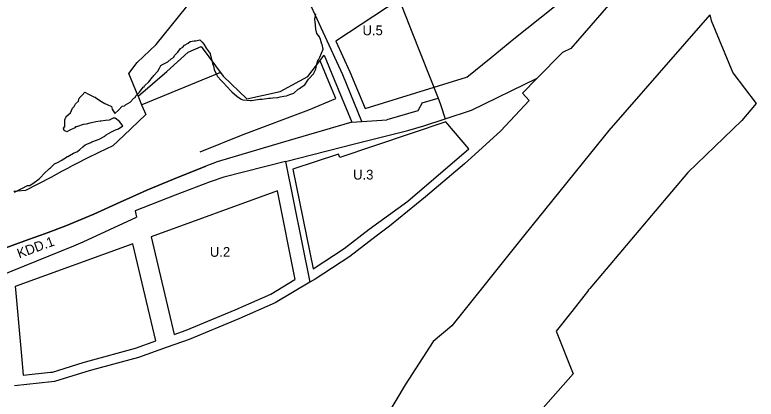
# Model space of a CAD drawing. Extents: x 7423571 to 7425893, y 5544590 to 5545833.
# Drawn here: x 7424447.1 to 7424826.9, y 5544859.3 to 5545056.2 of the extents above; entities that cross this region are included whole.
import ezdxf

# ---------------------------------------------------------------- set-up
doc = ezdxf.new("R2010")
doc.units = 0
for name, color, linetype in [('Default', 7, 'Continuous'), ('linie_rozgraniczające', 7, 'Continuous'), ('linie_zabudowy_nieprzekraczalne', 7, 'Continuous'), ('linie_zabudowy_obowiązujace', 7, 'Continuous'), ('oznaczenia_przeznaczen', 7, 'Continuous')]:
    doc.layers.add(name, color=color, linetype=linetype)

msp = doc.modelspace()

# ---------------------------------------------------------------- linework, layer by layer
at = {"layer": 'Default'}
msp.add_lwpolyline([(7424446.81, 5544965.29), (7424449.22, 5544966.56), (7424449.88, 5544966.97), (7424450.11, 5544967.05), (7424450.64, 5544967.3), (7424453.54, 5544968.7), (7424454.81, 5544968.78), (7424457.02, 5544970.3), (7424458.82, 5544971.77), (7424459.67, 5544972.43), (7424459.83, 5544972.52), (7424460, 5544972.69), (7424462.19, 5544975.14), (7424464.48, 5544977.19), (7424464.87, 5544977.48), (7424465.25, 5544977.9), (7424467.44, 5544979.92), (7424469.34, 5544980.78), (7424470.88, 5544981.57), (7424473.57, 5544983.24), (7424473.88, 5544983.6), (7424474.22, 5544983.71), (7424475.07, 5544984.17), (7424477.14, 5544985.4), (7424479.12, 5544986.28), (7424480.45, 5544987.17), (7424481.91, 5544988.59), (7424483.02, 5544989.6), (7424483.98, 5544989.97), (7424486.08, 5544990.9), (7424486.57, 5544991.14), (7424488.9, 5544992.07), (7424490.33, 5544992.48), (7424493.16, 5544994.05), (7424493.39, 5544994.47), (7424493.79, 5544994.72), (7424495, 5544995.36), (7424496.64, 5544996.28), (7424498.69, 5544997.23), (7424500.16, 5544997.84), (7424502.46, 5544999.43), (7424500.71, 5545001.55), (7424498.45, 5545003.31), (7424497.43, 5545003.21), (7424495.44, 5545002.19), (7424493.49, 5545002.07), (7424491.34, 5545001.82), (7424490.79, 5545001.67), (7424488.51, 5545001.45), (7424486.42, 5545000.9), (7424485.51, 5545000.71), (7424483.56, 5545000.24), (7424482.15, 5545000.02), (7424479.09, 5544998.96), (7424478.61, 5544998.86), (7424478.17, 5544998.89), (7424477.72, 5544998.42), (7424474.94, 5544997.05), (7424473.71, 5544996.37), (7424472.4, 5544996.93), (7424472, 5544998.19), (7424472.74, 5544999.09), (7424472.73, 5545002.49), (7424472.94, 5545003.23), (7424473.12, 5545003.54), (7424473.39, 5545004.13), (7424475.6, 5545006.06), (7424476.61, 5545008.39), (7424477.39, 5545009.22), (7424478.14, 5545010.57), (7424479.61, 5545011.98), (7424480.07, 5545013.53), (7424481.51, 5545015.04), (7424482.9, 5545016.54), (7424484.8, 5545015.59), (7424487.62, 5545014.21), (7424488, 5545014.02), (7424488.16, 5545014.02), (7424488.47, 5545013.87), (7424491.09, 5545011.98), (7424493.14, 5545010.83), (7424494.29, 5545010.23), (7424496.6, 5545009.2), (7424496.91, 5545007.86), (7424498.35, 5545005.63), (7424500.16, 5545007.46), (7424502.02, 5545009.42), (7424503, 5545009.65), (7424503.19, 5545009.69), (7424503.77, 5545010.08), (7424506.18, 5545011.53), (7424508.04, 5545013.46), (7424508.76, 5545013.96), (7424509.1, 5545014.71), (7424511, 5545016.7), (7424512.82, 5545019.13), (7424513.26, 5545019.43), (7424513.5, 5545019.89), (7424515.78, 5545021.91), (7424517.61, 5545024.34), (7424518.02, 5545024.66), (7424518.28, 5545025.09), (7424520.3, 5545027.36), (7424521.16, 5545028.95), (7424521.95, 5545030.24), (7424522.16, 5545030.46), (7424522.36, 5545030.57), (7424523.01, 5545030.95), (7424525.5, 5545032.19), (7424527.24, 5545033.63), (7424528.28, 5545034.43), (7424529.01, 5545035.53), (7424530.63, 5545037.07), (7424532.03, 5545038.96), (7424533.08, 5545039.62), (7424534.08, 5545040.74), (7424535.92, 5545041.81), (7424536.89, 5545042.56), (7424538.87, 5545042.94), (7424539.88, 5545042.97), (7424541.85, 5545043.5), (7424543.04, 5545042.24), (7424543.87, 5545041.14), (7424545.08, 5545039.24), (7424547.14, 5545036.49), (7424547.2, 5545036.32), (7424547.21, 5545036.27), (7424547.23, 5545036.19), (7424548.09, 5545032.07), (7424548.32, 5545031.31), (7424548.8, 5545029.94), (7424549.28, 5545028.15), (7424550.06, 5545026.38), (7424550.86, 5545024.65), (7424552.71, 5545022.55), (7424553.28, 5545022.06), (7424553.88, 5545021.53), (7424555.68, 5545019.44), (7424557.93, 5545017.12), (7424558.13, 5545016.89), (7424558.31, 5545016.71), (7424560.73, 5545014.49), (7424563.1, 5545013.08), (7424563.93, 5545012.75), (7424567.83, 5545012.4), (7424568.14, 5545012.32), (7424568.33, 5545012.3), (7424572.38, 5545013), (7424573.11, 5545012.97), (7424573.78, 5545013), (7424577.09, 5545013.47), (7424578.09, 5545013.53), (7424579.23, 5545013.7), (7424581.8, 5545013.94), (7424583.07, 5545014.15), (7424584.87, 5545014.6), (7424586.2, 5545014.69), (7424588.03, 5545015.36), (7424589.95, 5545016.04), (7424592.26, 5545018.09), (7424592.66, 5545018.35), (7424592.9, 5545018.57), (7424594.22, 5545019.52), (7424595.67, 5545020.39), (7424597.23, 5545022.78), (7424597.61, 5545023.31), (7424597.65, 5545023.37), (7424597.71, 5545023.45), (7424600.05, 5545025.96), (7424601.26, 5545028.46), (7424601.43, 5545029.5), (7424602.32, 5545033.07), (7424602.62, 5545033.21), (7424602.82, 5545033.53), (7424603.28, 5545034.56), (7424604.16, 5545036.6), (7424605.09, 5545038.62), (7424604.47, 5545041.07), (7424604.45, 5545041.14), (7424603.77, 5545043.57), (7424603.18, 5545044.89), (7424601.77, 5545046.66), (7424601.43, 5545048.21), (7424601.36, 5545048.48), (7424601.29, 5545048.87), (7424600.96, 5545052.91), (7424600.84, 5545053.46), (7424600.81, 5545054.11), (7424601.36, 5545056.79)], dxfattribs=at)
at = {"layer": 'linie_rozgraniczające'}
for p, q in [((7424665.16, 5545010.33), (7424667.6, 5545002.99)), ((7424682.72, 5544984.69), (7424677.42, 5544979.9)), ((7424585.74, 5544981.08), (7424598.16, 5544919.27)), ((7424508.87, 5544954.94), (7424509.39, 5544952.57))]:
    msp.add_line(p, q, dxfattribs=at)
for points in [[(7424510.23, 5545014.49), (7424505.42, 5545026.19), (7424509.67, 5545031.79), (7424519.51, 5545041.02), (7424545.99, 5545074.08), (7424548.87, 5545077.67), (7424573.07, 5545087.42), (7424579.84, 5545090.14), (7424570.85, 5545108.27), (7424590.52, 5545122.25), (7424613.92, 5545138.89)], [(7424624.93, 5545001.63), (7424615.09, 5545025.48), (7424595.04, 5545069.35), (7424609.07, 5545077.36), (7424632.92, 5545092.15)], [(7424632.92, 5545092.15), (7424643.95, 5545064.26), (7424650.55, 5545047.57), (7424663.93, 5545013.46)], [(7424775.58, 5545091.16), (7424769.05, 5545083.95), (7424767.05, 5545080.56), (7424757.66, 5545069.92), (7424758.07, 5545069.2), (7424732, 5545039.05), (7424727.68, 5545037), (7424714.63, 5545023.76)], [(7424803.18, 5545056.25), (7424777.14, 5545026.47), (7424751.41, 5544997.02), (7424741.99, 5544985.34), (7424729.85, 5544970.27), (7424707.69, 5544942.78), (7424671.01, 5544896.81), (7424661.4, 5544888.86), (7424647.11, 5544866.62), (7424626.86, 5544832.84), (7424603.45, 5544771.66), (7424592.16, 5544740.37), (7424574.9, 5544685.08), (7424583.83, 5544671.17), (7424585.87, 5544639.76), (7424586.82, 5544615.18)], [(7424803.18, 5545056.25), (7424803.93, 5545053.38), (7424814.96, 5545026.45), (7424826.93, 5545010.87), (7424819.62, 5545002.17), (7424791.84, 5544975.38), (7424741.71, 5544916.05), (7424741.07, 5544915.24), (7424740.42, 5544914.42), (7424732.44, 5544904.28), (7424724.47, 5544894.13), (7424733.19, 5544872.33), (7424717.72, 5544854.88)], [(7424510.23, 5545014.49), (7424524.94, 5545027.27), (7424535.96, 5545037.1), (7424542.47, 5545039.95), (7424553.73, 5545024.82), (7424566, 5545013.26), (7424574.53, 5545015.07), (7424583.06, 5545016.89), (7424597.21, 5545024.69), (7424605.64, 5545035.52), (7424610.75, 5545023.14), (7424619.75, 5545001.28)], [(7424667.6, 5545002.99), (7424680.98, 5545007.44), (7424714.63, 5545023.76)], [(7424714.63, 5545023.76), (7424707.11, 5545016.09), (7424710.69, 5545012.37), (7424696.05, 5544996.85), (7424682.72, 5544984.69)], [(7424510.23, 5545014.49), (7424510.75, 5545013.23), (7424512.01, 5545010.17), (7424514.11, 5545005.09), (7424502.84, 5544994.44), (7424497.19, 5544989.06), (7424490.02, 5544985.68), (7424483.84, 5544982.54), (7424478.83, 5544980.02), (7424476.86, 5544979.02), (7424476.4, 5544978.79), (7424474.02, 5544977.51), (7424471.39, 5544976.1), (7424471.03, 5544975.91), (7424465.48, 5544972.96), (7424452.52, 5544966.27), (7424448.61, 5544965.87), (7424447.12, 5544965.72), (7424446.5, 5544965.65)], [(7424655.78, 5545011.09), (7424663.93, 5545013.46)], [(7424663.93, 5545013.46), (7424665.16, 5545010.33)], [(7424655.78, 5545011.09), (7424653.6, 5545007.04), (7424637.66, 5545002.5)], [(7424619.75, 5545001.28), (7424583.58, 5544990.64), (7424550.71, 5544980.98), (7424544.86, 5544978.63), (7424528.37, 5544972.02), (7424514.73, 5544966.36), (7424507.57, 5544963.11), (7424501.03, 5544960.27), (7424487.52, 5544954.03), (7424473.11, 5544948.04), (7424462.84, 5544944.22), (7424454.11, 5544941.08), (7424437.17, 5544934.95)], [(7424585.74, 5544981.08), (7424621.19, 5544990.17), (7424648.5, 5544996.94), (7424656.67, 5544999.36), (7424667.6, 5545002.99)], [(7424619.75, 5545001.28), (7424624.93, 5545001.63)], [(7424624.93, 5545001.63), (7424637.66, 5545002.5)], [(7424585.74, 5544981.08), (7424554.07, 5544973.02), (7424547.15, 5544970.7), (7424529.22, 5544963.75), (7424508.69, 5544955.72), (7424508.87, 5544954.94)], [(7424677.42, 5544979.9), (7424657.43, 5544963.01), (7424638.99, 5544947.95), (7424632.15, 5544942.76), (7424618.73, 5544932.37), (7424600.98, 5544920.85), (7424598.16, 5544919.27)], [(7424432.84, 5544919.97), (7424477.32, 5544937.89), (7424482.11, 5544939.96), (7424509.39, 5544952.57)], [(7424598.16, 5544919.27), (7424580.47, 5544908.68), (7424561.86, 5544900.49), (7424536.44, 5544889.89), (7424525.12, 5544885.95), (7424510.47, 5544880.67), (7424486.42, 5544874.14), (7424483.47, 5544873.29), (7424467.38, 5544868.28), (7424465.8, 5544868.11), (7424446.88, 5544866.1)]]:
    msp.add_lwpolyline(points, dxfattribs=at)
at = {"layer": 'linie_zabudowy_nieprzekraczalne'}
for p, q in [((7424552.38, 5545026.63), (7424512.05, 5545010.07)), ((7424589.58, 5544977.22), (7424599.85, 5544926.08)), ((7424590.74, 5544920.65), (7424581.68, 5544966.06))]:
    msp.add_line(p, q, dxfattribs=at)
for points in [[(7424678.59, 5545024.29), (7424691.07, 5545034.32), (7424702.72, 5545043.98), (7424751.98, 5545083.18), (7424757.42, 5545088.33), (7424782.39, 5545110.2), (7424781.06, 5545112.49), (7424781.06, 5545112.49), (7424767.73, 5545135.35), (7424763.84, 5545142.04), (7424763.84, 5545142.05), (7424759.11, 5545150.24), (7424736.71, 5545138.34), (7424643.95, 5545064.26), (7424611.62, 5545042.69), (7424618.76, 5545027.07), (7424626.56, 5545008.17), (7424678.57, 5545024.27)], [(7424599.85, 5544926.08), (7424615.83, 5544936.45), (7424628.61, 5544946.34), (7424648.41, 5544960.74), (7424679.61, 5544987.5), (7424667.87, 5545001.41), (7424613.51, 5544983.15), (7424612.96, 5544984.9), (7424589.58, 5544977.22)], [(7424581.68, 5544966.06), (7424516.96, 5544942.42)], [(7424507.5, 5544938.97), (7424447.23, 5544917.05)], [(7424519.23, 5544889.14), (7424507.5, 5544938.97)], [(7424516.96, 5544942.42), (7424528.72, 5544892.5)], [(7424528.72, 5544892.5), (7424534.8, 5544894.61), (7424559.89, 5544905.09), (7424578.17, 5544913.13), (7424590.58, 5544920.56)], [(7424447.23, 5544917.05), (7424447.38, 5544915.44), (7424450.5, 5544881.5), (7424451.4, 5544871.61)], [(7424451.4, 5544871.61), (7424465.27, 5544873.08), (7424466.36, 5544873.2), (7424482.03, 5544878.08), (7424485.07, 5544878.96), (7424508.96, 5544885.44), (7424519.23, 5544889.14)]]:
    msp.add_lwpolyline(points, dxfattribs=at)
at = {"layer": 'linie_zabudowy_obowiązujace'}
for points in [[(7424611.46, 5545013.34), (7424607.91, 5545021.97), (7424603.47, 5545032.73)], [(7424542.08, 5544986), (7424563.99, 5544994.91), (7424597.74, 5545007.6), (7424611.46, 5545013.34)], [(7424437.17, 5544934.95), (7424454.11, 5544941.08), (7424462.84, 5544944.22), (7424473.11, 5544948.04), (7424487.52, 5544954.03), (7424501.03, 5544960.27), (7424507.57, 5544963.11), (7424514.73, 5544966.36), (7424528.37, 5544972.02), (7424544.86, 5544978.63)]]:
    msp.add_lwpolyline(points, dxfattribs=at)

# ---------------------------------------------------------------- texts
at = {"layer": 'oznaczenia_przeznaczen'}
for s, p in [('U.5', (7424625.22, 5545045.79)), ('U.3', (7424620.39, 5544971.83)), ('U.2', (7424546.99, 5544932.26))]:
    msp.add_text(s, height=5, dxfattribs=at).set_placement(p)
msp.add_text('KDD.1', height=5, rotation=20.2088, dxfattribs=at).set_placement((7424449.3, 5544931.37))

doc.saveas('drawing.dxf')
